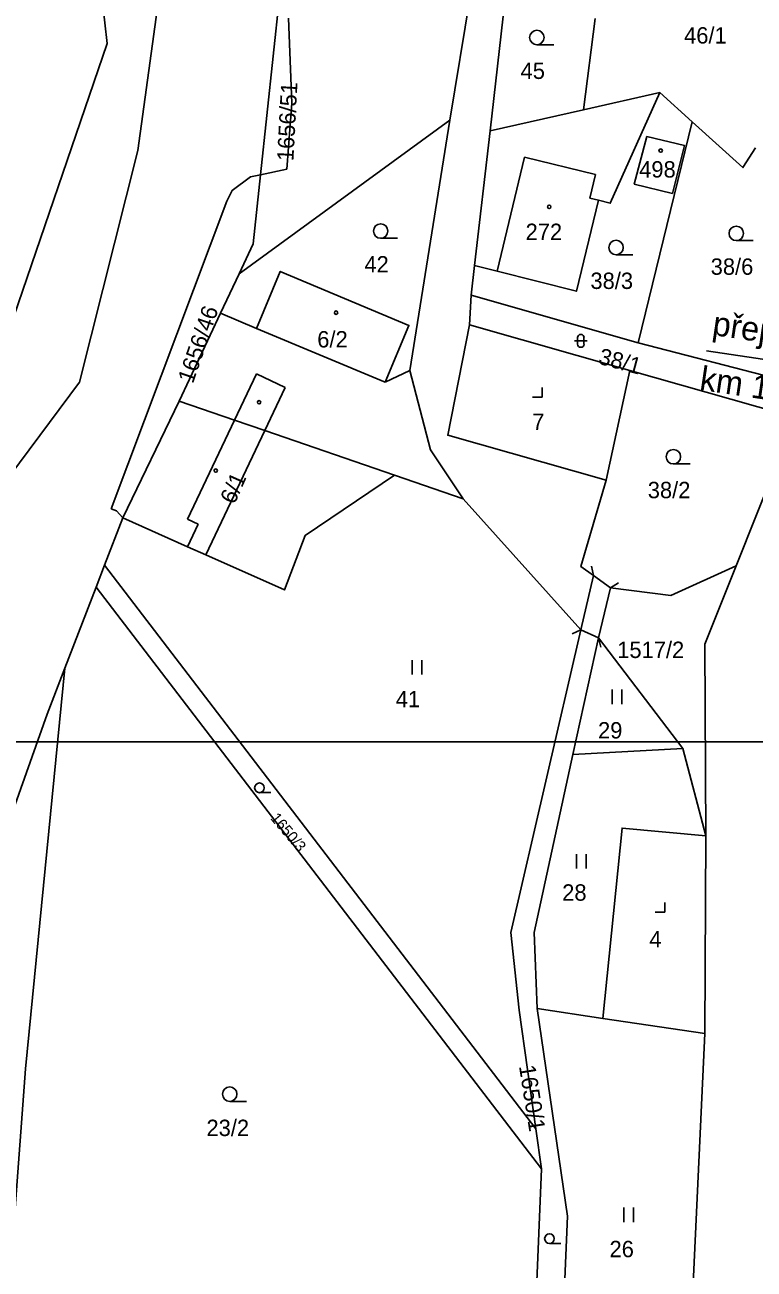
# Model space of a CAD drawing. Extents: x -553916 to -552953, y -1067469 to -1066637.
# Drawn here: x -553633.4 to -553557.7, y -1067154.7 to -1067025.6 of the extents above; entities that cross this region are included whole.
import ezdxf

# ---------------------------------------------------------------- set-up
doc = ezdxf.new("R2010")
doc.units = 0
for name, color, linetype in [('Hranice parcel', 7, 'Continuous'), ('Parcelní čísla', 7, 'Continuous'), ('Přejezd - štěrkové lože', 7, 'Continuous'), ('Vnitřní kresba', 7, 'Continuous'), ('Vrstva 1', 7, 'Continuous'), ('Značky budov', 7, 'Continuous'), ('Značky kultur', 7, 'Continuous')]:
    doc.layers.add(name, color=color, linetype=linetype)

msp = doc.modelspace()

# ---------------------------------------------------------------- linework, layer by layer
at = {"layer": 'Hranice parcel'}
for p, q in [((-553589.31, -1067035.5), (-553580.85, -1066983.77)), ((-553608.97, -1067041.18), (-553606.12, -1067014.56)), ((-553575.44, -1067034.44), (-553574.24, -1067024.96)), ((-553567.53, -1067032.65), (-553575.44, -1067034.44)), ((-553564.16, -1067035.68), (-553567.53, -1067032.65)), ((-553575.44, -1067034.44), (-553585.14, -1067036.63)), ((-553589.31, -1067035.5), (-553611.2, -1067051.45)), ((-553593.47, -1067061.49), (-553589.31, -1067035.5)), ((-553569.79, -1067058.6), (-553564.16, -1067035.68)), ((-553585.14, -1067036.63), (-553586.75, -1067050.6)), ((-553610, -1067041.4), (-553608.97, -1067041.18)), ((-553606.25, -1067040.6), (-553608.97, -1067041.18)), ((-553611.2, -1067051.45), (-553613.12, -1067055.53)), ((-553586.75, -1067050.6), (-553587.12, -1067053.68)), ((-553586.75, -1067050.6), (-553584.42, -1067051.17)), ((-553587.12, -1067053.68), (-553587.28, -1067056.75)), ((-553569.79, -1067058.6), (-553587.12, -1067053.68)), ((-553613.12, -1067055.53), (-553617.4, -1067064.65)), ((-553609.37, -1067057.11), (-553613.12, -1067055.53)), ((-553570.64, -1067061.48), (-553587.28, -1067056.75)), ((-553553.65, -1067062.79), (-553569.79, -1067058.6)), ((-553593.47, -1067061.49), (-553596.05, -1067062.7)), ((-553573.09, -1067072.86), (-553570.64, -1067061.48)), ((-553570.64, -1067061.48), (-553554.35, -1067066.11)), ((-553617.4, -1067064.65), (-553623.27, -1067076.77)), ((-553559.6, -1067081.76), (-553555.44, -1067071.33)), ((-553595.06, -1067072.35), (-553587.94, -1067074.8)), ((-553575.72, -1067088.37), (-553587.94, -1067074.8)), ((-553623.27, -1067076.77), (-553625.16, -1067081.69)), ((-553625.16, -1067081.69), (-553626.04, -1067083.95)), ((-553625.16, -1067081.69), (-553580.41, -1067140.15)), ((-553575.72, -1067088.37), (-553574.42, -1067082.75)), ((-553574.42, -1067082.75), (-553572.66, -1067084.02)), ((-553626.04, -1067083.95), (-553629.28, -1067092.37)), ((-553579.82, -1067144.32), (-553626.04, -1067083.95)), ((-553572.66, -1067084.02), (-553573.91, -1067089.23)), ((-553573.91, -1067089.23), (-553576.54, -1067101.32)), ((-553565.13, -1067100.69), (-553573.91, -1067089.23)), ((-553565.13, -1067100.69), (-553576.54, -1067101.32)), ((-553562.76, -1067109.76), (-553565.13, -1067100.69)), ((-553562.87, -1067130.27), (-553562.76, -1067109.76)), ((-553573.45, -1067128.7), (-553580.27, -1067127.69)), ((-553573.45, -1067128.7), (-553562.87, -1067130.27)), ((-553580.41, -1067140.15), (-553579.82, -1067144.32)), ((-553581.09, -1067176.52), (-553579.82, -1067144.32))]:
    msp.add_line(p, q, dxfattribs=at)
for points in [[(-553623.32, -1066984.67), (-553619.63, -1066996.83), (-553619.56, -1067023.02), (-553621.7, -1067038.64), (-553627.75, -1067062.69), (-553642.34, -1067082.27), (-553644.52, -1067088.87), (-553655.73, -1067178.24), (-553657.73, -1067185.13), (-553660.17, -1067189.87)], [(-553635.52, -1067058.6), (-553624.9, -1067027.54), (-553625.87, -1067018.94)], [(-553582.25, -1067023.44), (-553583.62, -1067023.18), (-553585.14, -1067036.63)], [(-553606.05, -1067024.93), (-553605.71, -1067033.75), (-553606.25, -1067040.6)], [(-553573.91, -1067043.82), (-553572.67, -1067044.12), (-553567.53, -1067032.65)], [(-553557.59, -1067038.38), (-553558.91, -1067040.42), (-553564.16, -1067035.68)], [(-553568.89, -1067037.19), (-553570.19, -1067042.13), (-553566.22, -1067043.1), (-553564.98, -1067038.12), (-553568.89, -1067037.19)], [(-553608.97, -1067041.18), (-553609.73, -1067048.33), (-553611.2, -1067051.45)], [(-553624.48, -1067075.84), (-553612.48, -1067043.92), (-553611.9, -1067042.79), (-553610, -1067041.4)], [(-553584.42, -1067051.17), (-553576.18, -1067053.25), (-553573.91, -1067043.82)], [(-553596.05, -1067062.7), (-553593.57, -1067056.8), (-553606.92, -1067051.2), (-553609.37, -1067057.11)], [(-553587.28, -1067056.75), (-553589.54, -1067068.19), (-553573.09, -1067072.86)], [(-553587.94, -1067074.8), (-553591.32, -1067069.72), (-553593.47, -1067061.49)], [(-553595.06, -1067072.35), (-553608.53, -1067067.7), (-553611.68, -1067066.62), (-553617.4, -1067064.65)], [(-553623.27, -1067076.77), (-553616.54, -1067079.76), (-553614.66, -1067080.6), (-553606.47, -1067084.24), (-553604.34, -1067078.59), (-553595.06, -1067072.35)], [(-553573.09, -1067072.86), (-553575.74, -1067081.8), (-553574.42, -1067082.75)], [(-553623.27, -1067076.77), (-553623.9, -1067076.05), (-553624.48, -1067075.84)], [(-553572.66, -1067084.02), (-553566.4, -1067084.81), (-553559.6, -1067081.76)], [(-553562.76, -1067109.76), (-553562.85, -1067089.89), (-553559.6, -1067081.76)], [(-553580.41, -1067140.15), (-553582.14, -1067127.86), (-553583, -1067119.78), (-553575.72, -1067088.37)], [(-553629.28, -1067092.37), (-553631.12, -1067097.14), (-553637.98, -1067116.48)], [(-553629.28, -1067092.37), (-553633.37, -1067133.92), (-553635.66, -1067164.7)], [(-553576.54, -1067101.32), (-553580.57, -1067119.79), (-553580.27, -1067127.69)], [(-553562.76, -1067109.76), (-553571.44, -1067108.95), (-553573.45, -1067128.7)], [(-553580.27, -1067127.69), (-553577.12, -1067149.23), (-553578.28, -1067177), (-553579.68, -1067182.05)], [(-553569.54, -1067184.03), (-553564.06, -1067156.23), (-553562.87, -1067130.27)]]:
    msp.add_lwpolyline(points, dxfattribs=at)
at = {"layer": 'Přejezd - štěrkové lože'}
msp.add_lwpolyline([(-553562.67, -1067059.43), (-553524.03, -1067065.17), (-553517.87, -1067076.06), (-553504.74, -1067077.98)], dxfattribs=at)
at = {"layer": 'Vnitřní kresba'}
for p, q in [((-553581.57, -1067039.35), (-553584.42, -1067051.17)), ((-553574.19, -1067041.13), (-553581.57, -1067039.35)), ((-553574.78, -1067043.61), (-553574.19, -1067041.13)), ((-553573.91, -1067043.82), (-553574.78, -1067043.61)), ((-553596.05, -1067062.7), (-553609.37, -1067057.11)), ((-553609.4, -1067061.81), (-553611.68, -1067066.62)), ((-553609.4, -1067061.81), (-553606.41, -1067063.23)), ((-553608.53, -1067067.7), (-553606.41, -1067063.23)), ((-553616.56, -1067076.9), (-553611.68, -1067066.62)), ((-553614.66, -1067080.6), (-553608.53, -1067067.7)), ((-553616.56, -1067076.9), (-553615.43, -1067077.44)), ((-553616.54, -1067079.76), (-553615.43, -1067077.44)), ((-553574.63, -1067081.77), (-553574.42, -1067082.75)), ((-553571.8, -1067083.51), (-553572.66, -1067084.02)), ((-553576.63, -1067088.79), (-553575.72, -1067088.37)), ((-553575.72, -1067088.37), (-553573.91, -1067089.23)), ((-553573.64, -1067090.19), (-553573.91, -1067089.23))]:
    msp.add_line(p, q, dxfattribs=at)
at = {"layer": 'Vrstva 1'}
for points in [[(-553300, -1066816.27), (-553300, -1067100), (-553800, -1067100), (-553800, -1066816.27)], [(-553800, -1067410.27), (-553800, -1067100), (-553300, -1067100), (-553300, -1067410.27)]]:
    msp.add_lwpolyline(points, dxfattribs=at)
at = {"layer": 'Značky budov'}
for centre in [(-553567.44, -1067038.66), (-553579, -1067044.5), (-553601.13, -1067055.48), (-553609.12, -1067064.77), (-553613.62, -1067071.87)]:
    msp.add_circle(centre, 0.175, dxfattribs=at)
at = {"layer": 'Značky kultur'}
for p, q in [((-553580.29, -1067027.68), (-553578.54, -1067027.68)), ((-553596.5, -1067047.76), (-553594.75, -1067047.76)), ((-553559.59, -1067048), (-553557.84, -1067048)), ((-553572.07, -1067049.47), (-553570.32, -1067049.47)), ((-553576.07, -1067058.06), (-553576.07, -1067058.74)), ((-553575.4, -1067058.74), (-553575.4, -1067058.06)), ((-553576.4, -1067058.4), (-553575.06, -1067058.4)), ((-553579.73, -1067064.23), (-553579.73, -1067063.23)), ((-553580.73, -1067064.23), (-553579.73, -1067064.23)), ((-553566.12, -1067071.18), (-553564.37, -1067071.18)), ((-553593.23, -1067093.03), (-553593.23, -1067091.53)), ((-553592.23, -1067093.03), (-553592.23, -1067091.53)), ((-553572.46, -1067096.09), (-553572.46, -1067094.59)), ((-553571.46, -1067096.09), (-553571.46, -1067094.59)), ((-553609.07, -1067105.28), (-553607.9, -1067105.28)), ((-553576.19, -1067113.16), (-553576.19, -1067111.66)), ((-553575.19, -1067113.16), (-553575.19, -1067111.66)), ((-553567.02, -1067117.68), (-553567.02, -1067116.68)), ((-553568.02, -1067117.68), (-553567.02, -1067117.68)), ((-553612.17, -1067137.31), (-553610.42, -1067137.31)), ((-553571.26, -1067149.83), (-553571.26, -1067148.33)), ((-553570.26, -1067149.83), (-553570.26, -1067148.33)), ((-553578.97, -1067152.05), (-553577.8, -1067152.05))]:
    msp.add_line(p, q, dxfattribs=at)
for centre, radius in [((-553580.29, -1067026.93), 0.75), ((-553596.5, -1067047.01), 0.75), ((-553559.59, -1067047.25), 0.75), ((-553572.07, -1067048.72), 0.75), ((-553566.12, -1067070.43), 0.75), ((-553609.08, -1067104.78), 0.502), ((-553612.17, -1067136.56), 0.75), ((-553578.98, -1067151.55), 0.502)]:
    msp.add_circle(centre, radius, dxfattribs=at)
for centre, start, end in [((-553575.73, -1067058.07), 0, 180), ((-553575.73, -1067058.74), 180, 359.9879)]:
    msp.add_arc(centre, 0.335, start, end, dxfattribs=at)

# ---------------------------------------------------------------- texts
at = {"layer": 'Parcelní čísla'}
for s, p in [('46/1', (-553565.01, -1067027.56)), ('45', (-553581.98, -1067031.23)), ('498', (-553569.67, -1067041.46)), ('272', (-553581.46, -1067047.94)), ('42', (-553598.19, -1067051.31)), ('38/6', (-553562.25, -1067051.55)), ('38/3', (-553574.73, -1067053.02)), ('6/2', (-553603.08, -1067059.09)), ('7', (-553580.77, -1067067.65)), ('38/2', (-553568.78, -1067074.73)), ('1517/2', (-553571.95, -1067091.31)), ('41', (-553594.93, -1067096.42)), ('29', (-553573.94, -1067099.66)), ('28', (-553577.66, -1067116.49)), ('4', (-553568.62, -1067121.33)), ('23/2', (-553614.58, -1067140.91)), ('26', (-553572.75, -1067153.48))]:
    msp.add_text(s, height=1.7, dxfattribs=at).set_placement(p)
for s, height, rotation, p in [('1656/51', 1.7, 87, (-553605.56, -1067039.79)), ('1656/46', 1.7, 71, (-553615.99, -1067062.91)), ('38/1', 1.7, 345, (-553574, -1067060.76)), ('6/1', 1.7, 66, (-553611.68, -1067075.45)), ('1650/3', 1.14, 310, (-553608.01, -1067107.95)), ('1650/1', 1.7, 279, (-553582.15, -1067133.66))]:
    msp.add_text(s, height=height, rotation=rotation, dxfattribs=at).set_placement(p)
at = {"layer": 'Přejezd - štěrkové lože'}
for s, p in [('přejezd P9170', (-553562.17, -1067057.78)), ('km 10,035', (-553563.49, -1067063.48))]:
    msp.add_text(s, height=2.5, rotation=351.5622, dxfattribs=at).set_placement(p)

doc.saveas('drawing.dxf')
